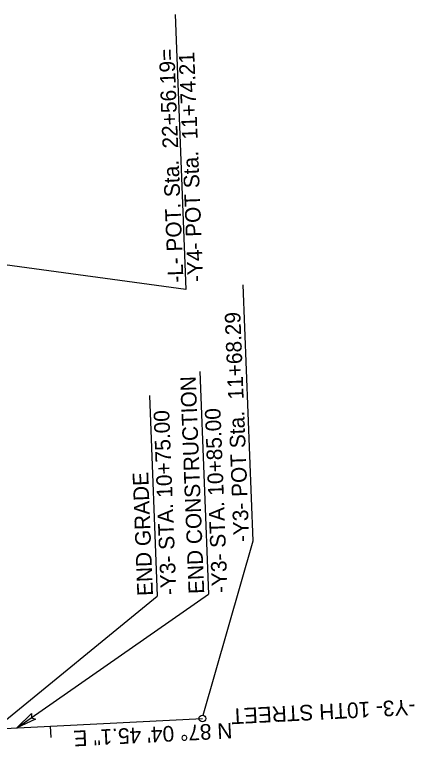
# Model space of a CAD drawing. Extents: x 1627861 to 1629601, y 761281 to 766239.
# Drawn here: x 1628554.1 to 1628733.4, y 762503.2 to 762831.5 of the extents above; entities that cross this region are included whole.
import ezdxf

# ---------------------------------------------------------------- set-up
doc = ezdxf.new("R2010")
doc.units = 0
for name, color, linetype in [('Cogo Default Point CELL', 7, 'Continuous'), ('Exist Other Culture Sign Leader', 7, 'Continuous'), ('Exist Property Tie Line Text', 7, 'Continuous'), ('Exist Right of Way Line Leader', 7, 'Continuous'), ('Exist Utilities Gas Meter CELL', 7, 'Continuous'), ('Exist Utilities Gas Meter Cogo Number', 7, 'Continuous'), ('Scratch_Level_0', 7, 'Continuous')]:
    doc.layers.add(name, color=color, linetype=linetype)

msp = doc.modelspace()

# ---------------------------------------------------------------- linework, layer by layer
at = {"layer": 'Exist Property Tie Line Text'}
msp.add_line((1628570.12, 762512.25), (1628570.38, 762507.26), dxfattribs=at)
at = {"layer": 'Exist Right of Way Line Leader'}
for p, q in [((1628626.07, 762831.52), (1628630.93, 762708.24)), ((1628630.93, 762708.24), (1628462.9, 762730.95)), ((1628661.1, 762595.39), (1628656.57, 762710.3)), ((1628638.74, 762517.17), (1628661.1, 762595.39))]:
    msp.add_line(p, q, dxfattribs=at)
msp.add_circle((1628638.33, 762515.73), 1.5, dxfattribs=at)
at = {"layer": 'Exist Utilities Gas Meter CELL'}
msp.add_line((1628470.25, 762507.16), (1628638.33, 762515.73), dxfattribs=at)
msp.add_line((1628470.25, 762507.16), (1628638.33, 762515.73), dxfattribs=at)
at = {"layer": 'Exist Utilities Gas Meter Cogo Number'}
msp.add_lwpolyline([(1628563.41, 762515.37), (1628555.14, 762511.49), (1628561.64, 762517.98), (1628561.62, 762516.01)], close=True, dxfattribs=at)
at = {"layer": 'Scratch_Level_0'}
for p, q in [((1628637.15, 762671.42), (1628641.09, 762571.56)), ((1628614.55, 762660.69), (1628618.1, 762570.65)), ((1628545.15, 762510.98), (1628618.1, 762570.65)), ((1628555.14, 762511.49), (1628641.09, 762571.56))]:
    msp.add_line(p, q, dxfattribs=at)

# ---------------------------------------------------------------- texts
at = {"layer": 'Cogo Default Point CELL'}
msp.add_text('N 87%%d 04\' 45.1" E', height=7, rotation=182.9208, dxfattribs=at).set_placement((1628651.58, 762513.82))
at = {"layer": 'Exist Other Culture Sign Leader'}
for s, rotation, p in [('END CONSTRUCTION', 92.2582, (1628639.18, 762571.75)), ('-Y3- STA. 10+75.00', 92.2582, (1628626.68, 762571.26)), ('-Y3- STA. 10+85.00', 92.2582, (1628649.67, 762572.17)), ('END GRADE', 92.2582, (1628616.19, 762570.85)), ('-Y3- 10TH STREET', 182.9208, (1628733.67, 762524.35))]:
    msp.add_text(s, height=7, rotation=rotation, dxfattribs=at).set_placement(p)
at = {"layer": 'Exist Right of Way Line Leader'}
for s, p in [('-L- POT. Sta.  22+56.19= ', (1628629.88, 762711.34)), ('-Y4- POT Sta.  11+74.21', (1628638.75, 762711.69)), ('-Y3- POT Sta.  11+68.29', (1628659.39, 762595.03))]:
    msp.add_text(s, height=7, rotation=92.2582, dxfattribs=at).set_placement(p)

doc.saveas('drawing.dxf')
